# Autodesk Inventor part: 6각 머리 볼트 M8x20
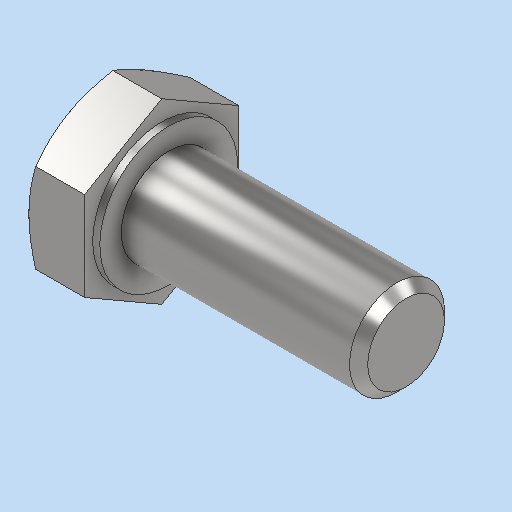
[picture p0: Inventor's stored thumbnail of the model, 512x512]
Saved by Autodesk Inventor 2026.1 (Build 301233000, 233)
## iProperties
Created: 2025-11
Part Number: 6각 머리 볼트 M8x20
Material: 강철, 연강
Description: 6각 머리 볼트 및 6각 머리 나사
Document SubType Name: Modeling
Designer: PC-30
Density: 7.85 g/cm^3
Appearance: 기본값
Author: jhkim
Sending System: Autodesk Inventor 2026
Preprocessor: ST-DEVELOPER v20.1
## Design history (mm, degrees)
feature "Solid1"
node "솔리드1"
